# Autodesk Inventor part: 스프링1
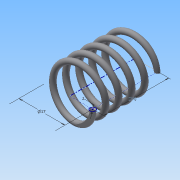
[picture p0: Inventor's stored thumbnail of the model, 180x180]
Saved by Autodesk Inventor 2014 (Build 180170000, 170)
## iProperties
Created: 2016-01
Part Number: 스프링1
Material: 강철, 탄소
Document SubType Name: Modeling
Designer: Administrator
Density: 1 g/cm^3
Appearance: 반연마
Author: Administrator
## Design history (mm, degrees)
sketch "스케치1"
  geometry: L1 (0, 0)-(8.5, 0); L2 (8.5, 0)-(8.5, 20.5); L3 (8.5, 20.5)-(0, 20.5); L4 (0, 20.5)-(0, 0); C1 r 1 at (8.5, 0)
  constraints: 8 end point, 2 parallel, 1 centre point, 1 coincident, 1 horizontal, 1 perpendicular
  dimensions: "d0" = 17 diameter of L2 L4; "d1" = 20.5 distance of L1.end L2.end (derived); "d2" = 2 diameter of C1
feature "코일1" sketch "스케치1" pitch "d3" = 10; turns "d5" = 5; dims "d4" = 20.5 (= d1), "d6" = 0, angle "d7" = 90 deg, angle "d8" = 90 deg, "d9" = 0, "d10" = 0
node "작업 평면2"
  node "작업 평면1"
sketch "스케치2"
  geometry: L1 (-9.5, 0)-(-7.5, 0) reference; 1 further point
  constraints: 1 horizontal alignment
extrude "돌출1" cut sketch "스케치2" stored distance "d13" = 10; taper "d14" = 0 deg
sketch "스케치3"
  geometry: L1 (-7.5, 0)-(-9.5, 0) reference; 1 further point
  constraints: 1 horizontal alignment
extrude "돌출2" cut sketch "스케치3" stored distance "d15" = 10; taper "d16" = 0 deg
node "솔리드1"
node "절단 모서리 투영1"
node "절단 모서리 투영2"
other parameters: "d11" = 0, "d12" = 20.5 (= d1)
